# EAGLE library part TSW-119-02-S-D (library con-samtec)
THROUGH-HOLE .025" SQ POST HEADER Source: Samtec TSW.pdf
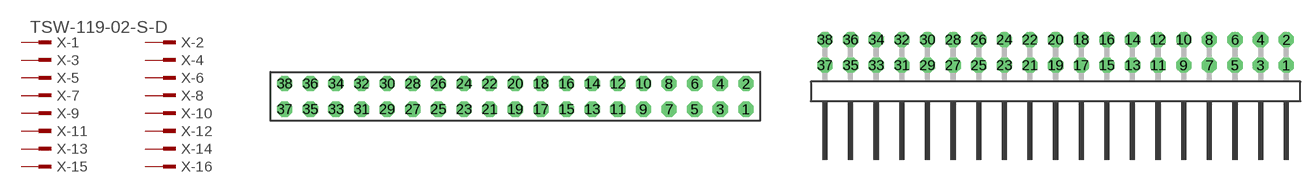
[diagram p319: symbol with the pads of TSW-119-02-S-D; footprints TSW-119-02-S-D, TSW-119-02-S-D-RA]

Designator prefix X; gates -1=MPINV -2=MPIN -3=MPIN -4=MPIN -5=MPIN -6=MPIN -7=MPIN -8=MPIN -9=MPIN -10=MPIN -11=MPIN -12=MPIN -13=MPIN -14=MPIN -15=MPIN -16=MPIN -17=MPIN -18=MPIN -19=MPIN -20=MPIN -21=MPIN -22=MPIN -23=MPIN -24=MPIN -25=MPIN -26=MPIN -27=MPIN -28=MPIN -29=MPIN -30=MPIN -31=MPIN -32=MPIN -33=MPIN -34=MPIN -35=MPIN -36=MPIN -37=MPIN -38=MPIN

## TSW-119-02-S-D (OC_FARNELL: unknown; OC_NEWARK: unknown)  [TSW-119-02-S-D]
1  -1:1  pas
2  -2:1  pas
3  -3:1  pas
4  -4:1  pas
5  -5:1  pas
6  -6:1  pas
7  -7:1  pas
8  -8:1  pas
9  -9:1  pas
10  -10:1  pas
11  -11:1  pas
12  -12:1  pas
13  -13:1  pas
14  -14:1  pas
15  -15:1  pas
16  -16:1  pas
17  -17:1  pas
18  -18:1  pas
19  -19:1  pas
20  -20:1  pas
21  -21:1  pas
22  -22:1  pas
23  -23:1  pas
24  -24:1  pas
25  -25:1  pas
26  -26:1  pas
27  -27:1  pas
28  -28:1  pas
29  -29:1  pas
30  -30:1  pas
31  -31:1  pas
32  -32:1  pas
33  -33:1  pas
34  -34:1  pas
35  -35:1  pas
36  -36:1  pas
37  -37:1  pas
38  -38:1  pas

## TSW-119-02-S-D-RA (OC_FARNELL: unknown; OC_NEWARK: unknown)  [TSW-119-02-S-D-RA]
Pads as for TSW-119-02-S-D

## Footprint TSW-119-02-S-D (pad centres in mm)
THROUGH-HOLE .025" SQ POST HEADER Source: Samtec TSW.pdf
drill 1 pad 1.5 octagon: 1 22.86,-1.27; 2 22.86,1.27; 3 20.32,-1.27; 4 20.32,1.27; 5 17.78,-1.27; 6 17.78,1.27; 7 15.24,-1.27; 8 15.24,1.27; 9 12.7,-1.27; 10 12.7,1.27; 11 10.16,-1.27; 12 10.16,1.27; 13 7.62,-1.27; 14 7.62,1.27; 15 5.08,-1.27; 16 5.08,1.27; 17 2.54,-1.27; 18 2.54,1.27; 19 0,-1.27; 20 0,1.27; 21 -2.54,-1.27; 22 -2.54,1.27; 23 -5.08,-1.27; 24 -5.08,1.27; 25 -7.62,-1.27; 26 -7.62,1.27; 27 -10.16,-1.27; 28 -10.16,1.27; 29 -12.7,-1.27; 30 -12.7,1.27; 31 -15.24,-1.27; 32 -15.24,1.27; 33 -17.78,-1.27; 34 -17.78,1.27; 35 -20.32,-1.27; 36 -20.32,1.27; 37 -22.86,-1.27; 38 -22.86,1.27

## Footprint TSW-119-02-S-D-RA (pad centres in mm)
THROUGH-HOLE .025" SQ POST HEADER Source: Samtec TSW.pdf
drill 1 pad 1.5 octagon: 1 22.86,1.524; 2 22.86,4.064; 3 20.32,1.524; 4 20.32,4.064; 5 17.78,1.524; 6 17.78,4.064; 7 15.24,1.524; 8 15.24,4.064; 9 12.7,1.524; 10 12.7,4.064; 11 10.16,1.524; 12 10.16,4.064; 13 7.62,1.524; 14 7.62,4.064; 15 5.08,1.524; 16 5.08,4.064; 17 2.54,1.524; 18 2.54,4.064; 19 0,1.524; 20 0,4.064; 21 -2.54,1.524; 22 -2.54,4.064; 23 -5.08,1.524; 24 -5.08,4.064; 25 -7.62,1.524; 26 -7.62,4.064; 27 -10.16,1.524; 28 -10.16,4.064; 29 -12.7,1.524; 30 -12.7,4.064; 31 -15.24,1.524; 32 -15.24,4.064; 33 -17.78,1.524; 34 -17.78,4.064; 35 -20.32,1.524; 36 -20.32,4.064; 37 -22.86,1.524; 38 -22.86,4.064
